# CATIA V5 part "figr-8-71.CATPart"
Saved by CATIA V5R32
Part number: Part1
Bounding box of the stored display mesh (mm): x -81.893 to 81.893, y -175.508 to 175.508, z -150 to 146
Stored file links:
  D:\PROJECTS\Project 2022\CATIA V5 6R 2022\Resources\Part Files\c08_catia_v5_6r2022_prt\figr-8-71.CATPart
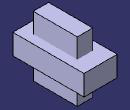
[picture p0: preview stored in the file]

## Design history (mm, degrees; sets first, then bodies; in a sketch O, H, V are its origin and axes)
Body1 (main body)
  Sketch1 on xy-plane, origin (0, 0, 0), H (1, 0, 0), V (0, 1, 0)
    line L1 (-81.8929, 175.5076) -> (81.8929, 175.5076)
    line L2 (81.8929, 175.5076) -> (81.8929, -175.5076)
    line L3 (81.8929, -175.5076) -> (-81.8929, -175.5076)
    line L4 (-81.8929, -175.5076) -> (-81.8929, 175.5076)
    axis line L5 (81.8929, -175.5076) -> (-81.8929, 175.5076)
    horizontal: L1 H, L3 H
    vertical: L2 V, L4 V
    midpoint: O L5
  Pad1: profile Sketch1, direction (0, 0, 1), length 50, mirrored extent
Body2
  Sketch2 on xy-plane, origin (0, 0, 0), H (1, 0, 0), V (0, 1, 0)
    line L1 (-37.4906, 99.3013) -> (38.4681, 99.3013)
    line L2 (38.4681, 99.3013) -> (38.4681, -118.5305)
    line L3 (38.4681, -118.5305) -> (-37.4906, -118.5305)
    line L4 (-37.4906, -118.5305) -> (-37.4906, 99.3013)
    horizontal: L1 H, L3 H
    vertical: L2 V, L4 V
  Pad2: profile Sketch2, direction (0, 0, 1), length 146, opposite side length 150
